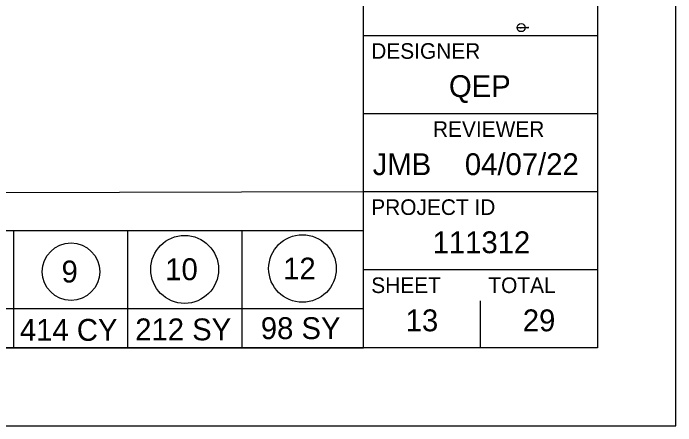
# Model space of a CAD drawing. Extents: x -34.1 to 34, y 0 to 22.
# Drawn here: x 29.758 to 34, y 0 to 2.642 of the extents above; entities that cross this region are included whole.
import ezdxf

# ---------------------------------------------------------------- set-up
doc = ezdxf.new("R2010")
doc.units = 0
for name, color, linetype in [('CS-ALGN-TEXT', 7, 'Continuous'), ('CS-ANNO', 7, 'Continuous'), ('CS-ANNO-MATC', 7, 'Continuous'), ('CS-ANNO-MATC-TEXT', 7, 'Continuous'), ('CS-ANNO-TABL', 7, 'Continuous')]:
    doc.layers.add(name, color=color, linetype=linetype)

msp = doc.modelspace()

# ---------------------------------------------------------------- linework, layer by layer
at = {"layer": 'CS-ALGN-TEXT'}
for p, q in [((25.488, 1.4832), (32, 1.5)), ((25.488, 1.25), (32, 1.25)), ((29.761, 0.5), (29.761, 1.25)), ((30.4909, 0.5), (30.4909, 1.25)), ((31.2244, 0.5), (31.2244, 1.25)), ((32.75, 0.5), (32.75, 0.8)), ((25.488, 0.75), (32, 0.75)), ((32.375, 0.675), (32.375, 0.675)), ((26.75, 0.5), (32, 0.5))]:
    msp.add_line(p, q, dxfattribs=at)
at = {"layer": 'CS-ANNO'}
msp.add_lwpolyline([(0, 0), (34, 0), (34, 22), (0, 22)], close=True, dxfattribs=at)
at = {"layer": 'CS-ANNO-MATC'}
for p, q in [((32, 0.5), (32, 21.5)), ((32, 2.5), (33.5, 2.5)), ((32, 2), (33.5, 2)), ((32, 1.5), (33.5, 1.5)), ((32, 1), (33.5, 1))]:
    msp.add_line(p, q, dxfattribs=at)
msp.add_lwpolyline([(1.5, 21.5), (33.5, 21.5), (33.5, 0.5), (1.5, 0.5)], close=True, dxfattribs=at)
at = {"layer": 'CS-ANNO-MATC-TEXT'}
for centre, radius in [((30.8553, 1.0013), 0.2175), ((31.6098, 1.007), 0.2165), ((30.1277, 0.9867), 0.1837)]:
    msp.add_circle(centre, radius, dxfattribs=at)
at = {"layer": 'CS-ANNO-TABL'}
for p, q in [((32.9838, 2.5498), (33.0359, 2.5498)), ((33.0101, 2.5498), (33.0596, 2.5498))]:
    msp.add_line(p, q, dxfattribs=at)
msp.add_circle((33.0099, 2.5498), 0.026, dxfattribs=at)

# ---------------------------------------------------------------- texts
at = {"layer": 'CS-ALGN-TEXT'}
for s, height, p in [('DESIGNER', 0.1, (32.05, 2.35)), ('QEP', 0.14, (32.5477, 2.105)), ('REVIEWER', 0.1, (32.4454, 1.85)), ('JMB', 0.14, (32.0596, 1.605)), ('04/07/22', 0.14, (32.6497, 1.605)), ('PROJECT ID', 0.1, (32.05, 1.35)), ('111312', 0.14, (32.4435, 1.105)), ('SHEET', 0.1, (32.05, 0.85)), ('TOTAL', 0.1, (32.8, 0.85)), ('13', 0.14, (32.2707, 0.605)), ('29', 0.14, (33.0206, 0.605))]:
    msp.add_text(s, height=height, dxfattribs=at).set_placement(p)
at = {"layer": 'CS-ANNO-MATC-TEXT'}
for s, p in [('10', (30.7312, 0.9323)), ('12', (31.4861, 0.9367)), ('9', (30.0672, 0.9176)), ('414 CY', (29.8007, 0.5439)), ('212 SY', (30.5391, 0.5471)), ('98 SY', (31.3431, 0.5549))]:
    msp.add_text(s, height=0.14, dxfattribs=at).set_placement(p)
at = {"layer": 'CS-ANNO-TABL'}
for s, p in [('2', (33.0087, 2.5563)), ('Drawing', (33.0427, 2.5563)), ('3+00.00', (33.0019, 2.5399)), ('1:2', (33.0427, 2.5399))]:
    msp.add_text(s, height=0.00328, dxfattribs=at).set_placement(p)

doc.saveas('drawing.dxf')
